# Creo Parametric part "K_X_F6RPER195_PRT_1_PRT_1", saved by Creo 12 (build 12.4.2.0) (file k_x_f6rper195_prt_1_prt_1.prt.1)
Units: Custom; MM, KILOGRAM, SECS

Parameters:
  PTC_WM_ITERATION = "0"
  PTC_WM_VERSION = "-.0"
  PTC_WM_LIFECYCLE_STATE = "In Work"
  PTC_WM_LIFECYCLE = "MO_CADDocument"
  PTC_WM_CREATED_BY = "Maximilian Roepper (Z0017RMS: MO)"
  PTC_WM_CREATED_ON = "18-Sep-26 11:36:42 AM"
  PTC_WM_MODIFIED_BY = "Maximilian Roepper (Z0017RMS: MO)"
  PTC_WM_MODIFIED_ON = "18-Sep-26 11:36:46 AM"
  PDMLINKNUMBER = "PDM000071454965"
  PTC_WM_NAME = "k_x_f6rper195_prt_1_prt_1.prt"
  PTC_WM_NUMBER = "PDM000071454965"

Other parameters: WEIGHT, WEIGHT_FACTOR, WEIGHT_ADD, _MASS_TEMP, _DIFF_TEMP, MC_ERRORS, SUPPLIER

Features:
  1. coordinate system
  2. datum plane "PRT_YZ"
  3. datum plane "PRT_XY"
  4. datum plane "PRT_XZ"
  5. coordinate system
  6. datum axis
  7. datum axis
  8. datum axis
  9. coordinate system
  10. imported feature
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
Other named items: PRT, SIEMENS_MO, DRW_VIEW_ORG, PRT_X, PRT_Y, PRT_Z, CS0, ROUGH_GROB

Layers: 00_STD_CSYS-KSYS, 01_STD_PLANES-EBENEN, 02_STD_AXES-ACHSEN, 03_STD_CSYS-KSYS, 24_IMPORT_FEAT-IMPORT_KE

Surfaces: 6 plane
